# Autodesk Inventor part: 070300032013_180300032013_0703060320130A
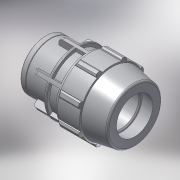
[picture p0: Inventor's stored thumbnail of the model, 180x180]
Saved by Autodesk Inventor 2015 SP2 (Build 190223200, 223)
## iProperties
Created: 2017-02
Part Number: 070300032013_180300032013_0703060320130A
Material: PVC-Piping
Description: PLASSON FEMALE ADAPTOR 32-1.1/4"
Document SubType Name: Modeling
Designer: KIM
Mass: 92.6774 g
Surface Area: 199.44 cm^2
Volume: 66.1981 cm^3
Density: 1.4 g/cm^3
Appearance: Smooth - White
Author: KIM
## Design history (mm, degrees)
derived "07030.ipt"
feature "Solid1::07030.ipt"
tag "TaggingFeature1"
body "Solid1"
other parameters: "d2" = 32, "d4" = 13.71429, "d5" = 24, "d7" = 64, "d9" = 13.71429, "d11" = 2.74286, "d12" = 51.2, "d13" = 120 deg, "d14" = 48, "d15" = 10 deg, "d16" = 57.6, "d18" = 1.6, "d19" = 35 deg, "d20" = 17.5 deg, "d21" = 59.52, "d23" = 0, "d25" = 360 deg, "d27" = 1.28, "d34" = 3.2, "d35" = 28.8, "d36" = 0, "d42" = 24, "d43" = 1.92, "d46" = 0.96, "d49" = 67, "d51" = 96, "d53" = 0.64, "d55" = 360 deg, "d61" = 25, "d62" = 25.6, "d63" = 38.952, "d64" = 32, "d65" = 3.2, "d66" = 0.5, "d67" = 1, "d68" = 7.5, "d69" = 46.08, "d70" = 1.6, "d_" = 32, "E_" = 64, "H_" = 96, "l_" = 67, "l_2" = 25, "Rp_" = 38.952
